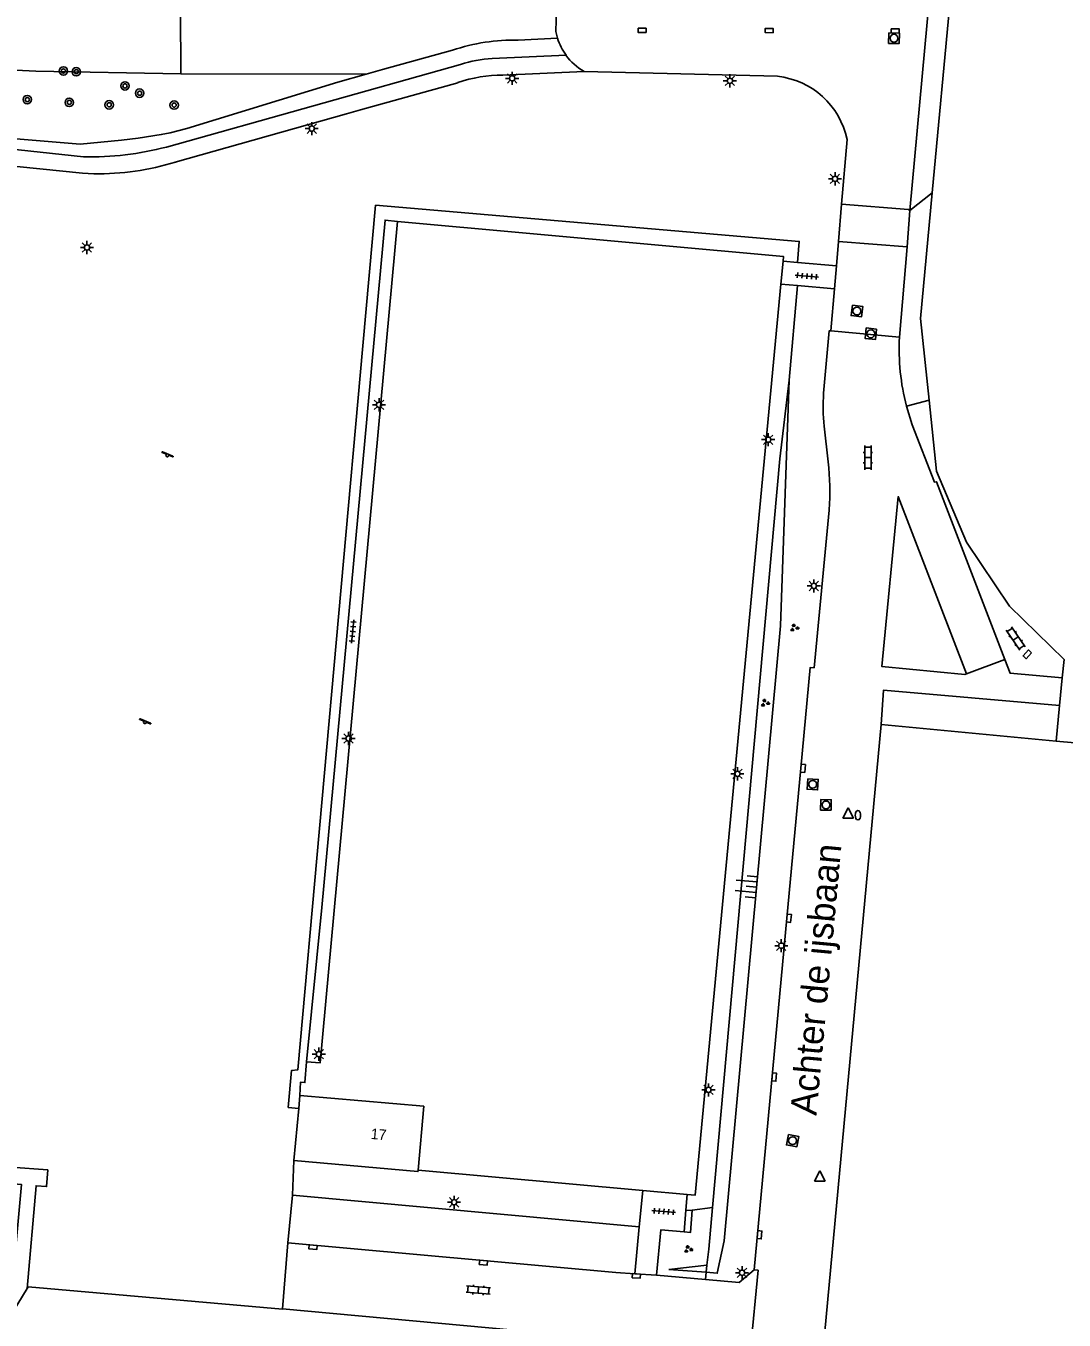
# Model space of a CAD drawing. Extents: x 132994 to 136000, y 393499 to 395512.
# Drawn here: x 133189.3 to 133287.9, y 394586 to 394708.9 of the extents above; entities that cross this region are included whole.
import ezdxf

# ---------------------------------------------------------------- set-up
doc = ezdxf.new("R2010")
doc.units = 0
for name, color, linetype in [('gg-afsc-hekwerk', 7, 'Continuous'), ('gg-anno-huisnummerreeks BGT', 7, 'Continuous'), ('gg-anno-openbare ruimte label', 7, 'Continuous'), ('gg-bbg-hoofdgebouw', 7, 'Continuous'), ('gg-bbg-tussenscheiding', 7, 'Continuous'), ('gg-knt-BGT kruinlijn', 7, 'Continuous'), ('gg-knt-bovenkant onderkant talud', 7, 'Continuous'), ('gg-knt-trap', 7, 'Continuous'), ('gg-knt-verharding', 7, 'Continuous'), ('gg-knt-verharding nz', 7, 'Continuous'), ('gt-grn-groengrens', 7, 'Continuous'), ('gt-symb-boom', 7, 'Continuous'), ('gt-symb-brandkraan', 7, 'Continuous'), ('gt-symb-groenvak', 7, 'Continuous'), ('gt-symb-klinker verharding', 7, 'Continuous'), ('gt-symb-kolk', 7, 'Continuous'), ('gt-symb-kolk center center', 7, 'Continuous'), ('gt-symb-lichtmast', 7, 'Continuous'), ('gt-symb-rioolschacht', 7, 'Continuous'), ('gt-symb-speelvoorziening', 7, 'Continuous'), ('gt-symb-talud symbool', 7, 'Continuous'), ('gt-symb-tegel verharding', 7, 'Continuous'), ('gt-symb-waterafsluiter', 7, 'Continuous')]:
    doc.layers.add(name, color=color, linetype=linetype)

# ---------------------------------------------------------------- blocks, each defined once
blk = doc.blocks.new('gt0-KL1')
at = {"layer": 'gt-symb-klinker verharding'}
for p, q in [((-1.15, 0.3), (1.15, 0.3)), ((-1, -0.3), (-1, 0.3)), ((-0.5, 0.3), (-0.5, 0.45)), ((0, -0.3), (0, 0.3)), ((0.5, 0.3), (0.5, 0.45)), ((1, -0.3), (1, 0.3)), ((-1.15, -0.3), (1.15, -0.3)), ((-0.5, -0.45), (-0.5, -0.3)), ((0.5, -0.45), (0.5, -0.3))]:
    blk.add_line(p, q, dxfattribs=at)
blk = doc.blocks.new('gt0-KOLKCC')
at = {"layer": 'gt-symb-kolk center center'}
blk.add_lwpolyline([(-0.38, 0.2), (0.38, 0.2), (0.38, -0.2), (-0.38, -0.2)], close=True, dxfattribs=at)
blk = doc.blocks.new('gt0-LMAST')
at = {"layer": 'gt-symb-lichtmast'}
for p, q in [((-0.18, 0.17), (-0.45, 0.44)), ((0, 0.25), (0, 0.62)), ((0.17, 0.17), (0.44, 0.44)), ((-0.25, 0), (-0.63, 0)), ((-0.18, -0.18), (-0.45, -0.45)), ((0, -0.25), (0, -0.63)), ((0.44, -0.45), (0.17, -0.18)), ((0.25, 0), (0.62, 0))]:
    blk.add_line(p, q, dxfattribs=at)
blk.add_circle((0, 0), 0.25, dxfattribs=at)
blk = doc.blocks.new('gt0-RS')
at = {"layer": 'gt-symb-rioolschacht'}
blk.add_lwpolyline([(-0.5, -0.5), (0.5, -0.5), (0.5, 0.5), (-0.5, 0.5)], close=True, dxfattribs=at)
blk.add_circle((0, 0), 0.375, dxfattribs=at)
blk = doc.blocks.new('gt0-WAFSL')
at = {"layer": 'gt-symb-waterafsluiter'}
for p, q in [((-0.5, -0.33), (0, 0.67)), ((0, 0.67), (0.5, -0.33)), ((0.5, -0.33), (-0.5, -0.33))]:
    blk.add_line(p, q, dxfattribs=at)
blk = doc.blocks.new('gt0-BR')
at = {"layer": 'gt-symb-brandkraan'}
for centre, radius, start, end in [((-0.24, 0), 0.206, 107.5669, 252.4331), ((0.6, -2.66), 3, 106.892, 107.5669), ((0, -0.69), 0.938, 73.108, 106.892), ((-0.6, -2.66), 3, 72.4331, 73.108), ((0.24, 0), 0.206, 287.567, 72.4331), ((0.6, 2.66), 3, 252.4331, 253.108), ((0, 0.69), 0.938, 253.108, 286.8921), ((-0.6, 2.66), 3, 286.8921, 287.567)]:
    blk.add_arc(centre, radius, start, end, dxfattribs=at)
blk = doc.blocks.new('gt0-TALUD_1')
at = {"layer": 'gt-symb-talud symbool'}
for p, q in [((-1, -1), (-1, 0)), ((-0.5, -2), (-0.5, 0)), ((0, -1), (0, 0)), ((0.5, -2), (0.5, 0)), ((1, -1), (1, 0))]:
    blk.add_line(p, q, dxfattribs=at)
blk = doc.blocks.new('gt0-GRVAK')
at = {"layer": 'gt-symb-groenvak'}
for p, q in [((-0.11, 0.19), (-0.23, 0.24)), ((-0.18, 0.15), (0.09, 0.15)), ((-0.09, 0.21), (-0.16, 0.32)), ((-0.05, 0.21), (-0.05, 0.39)), ((0, 0.21), (0.06, 0.32)), ((0.01, 0.19), (0.13, 0.24)), ((0.26, -0.05), (0.2, 0.06)), ((0.3, -0.05), (0.3, 0.13)), ((0.35, -0.05), (0.41, 0.06)), ((-0.25, -0.23), (-0.36, -0.18)), ((-0.32, -0.26), (-0.05, -0.26)), ((-0.23, -0.21), (-0.29, -0.1)), ((-0.18, -0.2), (-0.18, -0.02)), ((-0.14, -0.21), (-0.07, -0.1)), ((-0.12, -0.23), (0, -0.18)), ((0.24, -0.07), (0.12, -0.02)), ((0.17, -0.11), (0.44, -0.11)), ((0.37, -0.07), (0.49, -0.02))]:
    blk.add_line(p, q, dxfattribs=at)
blk = doc.blocks.new('gt0-KOLK')
at = {"layer": 'gt-symb-kolk'}
blk.add_lwpolyline([(0, 0), (0.37, 0), (0.37, 0.4), (-0.38, 0.4), (-0.38, 0), (0, 0)], dxfattribs=at)
blk = doc.blocks.new('gt0-TEG1')
at = {"layer": 'gt-symb-tegel verharding'}
for p, q in [((-1.13, 0), (1.12, 0)), ((-0.9, -0.25), (-0.9, 0.25)), ((-0.45, -0.25), (-0.45, 0.25)), ((0, -0.25), (0, 0.25)), ((0.45, -0.25), (0.45, 0.25)), ((0.9, -0.25), (0.9, 0.25))]:
    blk.add_line(p, q, dxfattribs=at)
blk = doc.blocks.new('gt0-SV')
at = {"layer": 'gt-symb-speelvoorziening'}
for p, q in [((-0.48, 0.26), (-0.08, 0.1)), ((0.54, -0.08), (-0.45, 0.32)), ((0.13, 0.01), (0.51, -0.14))]:
    blk.add_line(p, q, dxfattribs=at)
for centre, radius, start, end in [((-0.47, 0.29), 0.0369, 63.6251, 252.6602), ((0, -0.01), 0.128, 127.6866, 8.5986), ((0.53, -0.11), 0.0363, 243.5085, 72.5436)]:
    blk.add_arc(centre, radius, start, end, dxfattribs=at)
blk = doc.blocks.new('gt0-BOOM')
at = {"layer": 'gt-symb-boom'}
for radius in [0.4, 0.2]:
    blk.add_circle((0, 0), radius, dxfattribs=at)

msp = doc.modelspace()

# ---------------------------------------------------------------- linework, layer by layer
at = {"layer": 'gg-afsc-hekwerk'}
for p, q in [((133203.96, 394710.33), (133203.99, 394704.3)), ((133260.97, 394684.34), (133261.18, 394686.51)), ((133226.52, 394600.23), (133247.87, 394598.28)), ((133247.87, 394598.28), (133252.07, 394597.9))]:
    msp.add_line(p, q, dxfattribs=at)
for points in [[(133203.99, 394704.3), (133190.2, 394704.56), (133179.49, 394705.09)], [(133224.57, 394690.27), (133217.23, 394610.41), (133215.91, 394610.51)], [(133261.18, 394686.51), (133261.22, 394686.96), (133224.57, 394690.27)], [(133252.07, 394597.9), (133252.83, 394597.83), (133260.97, 394684.34)], [(133215.91, 394610.51), (133215.77, 394608.54), (133215.34, 394608.57), (133215.29, 394607.32)]]:
    msp.add_lwpolyline(points, dxfattribs=at)
at = {"layer": 'gg-bbg-hoofdgebouw'}
for p, q in [((133275.35, 394693.01), (133280.01, 394742.92)), ((133287.7, 394646.95), (133287.44, 394644.33)), ((133287.44, 394644.33), (133287.12, 394640.96)), ((133270.5, 394642.52), (133264.44, 394577.27)), ((133287.12, 394640.96), (133270.5, 394642.52)), ((133215.18, 394606.08), (133215.29, 394607.32)), ((133214.73, 394601.13), (133215.18, 394606.08))]:
    msp.add_line(p, q, dxfattribs=at)
for points in [[(133275.35, 394693.01), (133274.23, 394681.08), (133275.05, 394673.31)], [(133275.05, 394673.31), (133275.76, 394666.58), (133278.6, 394659.83), (133282.7, 394653.76), (133287.87, 394648.69), (133287.7, 394646.95)], [(133215.29, 394607.32), (133227.06, 394606.28), (133226.52, 394600.23)], [(133226.52, 394600.23), (133226.5, 394600.08), (133214.73, 394601.13)]]:
    msp.add_lwpolyline(points, dxfattribs=at)
at = {"layer": 'gg-bbg-tussenscheiding'}
msp.add_line((133287.12, 394640.96), (133358.95, 394634.21), dxfattribs=at)
at = {"layer": 'gg-knt-BGT kruinlijn'}
msp.add_line((133250.32, 394590.8), (133253.89, 394590.52), dxfattribs=at)
msp.add_lwpolyline([(133253.89, 394590.52), (133254.93, 394590.43), (133255.59, 394593.52), (133260.95, 394651.89), (133261.77, 394675.22)], dxfattribs=at)
at = {"layer": 'gg-knt-bovenkant onderkant talud'}
msp.add_line((133253.95, 394591.19), (133250.32, 394590.8), dxfattribs=at)
for points in [[(133261.77, 394675.22), (133260.89, 394667.74), (133254.49, 394596.66)], [(133254.49, 394596.66), (133254.14, 394592.71), (133253.95, 394591.19)]]:
    msp.add_lwpolyline(points, dxfattribs=at)
at = {"layer": 'gg-knt-trap'}
msp.add_lwpolyline([(133270.5, 394642.52), (133270.73, 394645.8), (133287.44, 394644.33)], dxfattribs=at)
at = {"layer": 'gg-knt-verharding'}
for p, q in [((133240.57, 394706.06), (133233.54, 394705.74)), ((133230.56, 394705.2), (133202.62, 394697.35)), ((133234.57, 394704.18), (133242.28, 394704.52)), ((133242.28, 394704.52), (133260.65, 394704.07)), ((133230.29, 394703.46), (133221.06, 394700.87)), ((133221.06, 394700.87), (133219.72, 394700.49)), ((133219.72, 394700.49), (133203.46, 394695.92)), ((133194.74, 394696.43), (133179.16, 394698.07)), ((133267.27, 394698.08), (133266.75, 394691.94)), ((133194.64, 394694.87), (133179.09, 394696.46)), ((133194.64, 394694.87), (133195.73, 394694.81)), ((133273.24, 394691.32), (133275.35, 394693.01)), ((133266.75, 394691.94), (133266.44, 394688.38)), ((133272.96, 394687.86), (133273.24, 394691.32)), ((133266.44, 394688.38), (133266.25, 394686.08)), ((133266.44, 394688.38), (133272.96, 394687.86)), ((133272.24, 394679.29), (133272.96, 394687.86)), ((133261.18, 394686.51), (133262.55, 394686.4)), ((133262.55, 394686.4), (133266.25, 394686.08)), ((133266.25, 394686.08), (133266.06, 394683.9)), ((133260.97, 394684.34), (133262.54, 394684.2)), ((133262.54, 394684.2), (133266.06, 394683.9)), ((133266.06, 394683.9), (133265.72, 394679.9)), ((133272.24, 394679.29), (133265.72, 394679.9)), ((133272.91, 394672.76), (133275.05, 394673.31)), ((133265.1, 394670.85), (133265.46, 394667.45)), ((133264.15, 394647.92), (133265.55, 394662.89)), ((133278.6, 394647.34), (133282.24, 394648.69)), ((133214.16, 394593.33), (133214.58, 394597.84)), ((133214.58, 394597.84), (133247.52, 394594.84)), ((133247.52, 394594.84), (133247.87, 394598.28)), ((133251.95, 394596.43), (133252.07, 394597.9)), ((133251.78, 394594.35), (133251.95, 394596.43)), ((133247.52, 394594.84), (133247.12, 394590.39)), ((133213.63, 394587.06), (133214.16, 394593.33)), ((133247.12, 394590.39), (133249.15, 394590.25)), ((133253.82, 394589.83), (133249.15, 394590.25)), ((133258.08, 394582.98), (133258.81, 394590.74)), ((133258.45, 394590.77), (133258.81, 394590.74)), ((133187.71, 394586.23), (133189.39, 394588.98)), ((133258.08, 394582.98), (133213.63, 394587.06))]:
    msp.add_line(p, q, dxfattribs=at)
for points in [[(133273.24, 394691.32), (133277.45, 394737.08), (133268.78, 394733.04)], [(133239.92, 394719.11), (133239.61, 394708.31), (133239.69, 394707.93), (133239.76, 394707.68)], [(133266.75, 394691.94), (133273.09, 394691.41), (133273.24, 394691.32)], [(133224.57, 394690.27), (133223.38, 394690.41), (133217.37, 394625.14), (133215.91, 394610.51)], [(133265.72, 394679.9), (133265.57, 394679.91), (133265.04, 394673.98)], [(133282.24, 394648.69), (133275.76, 394665.58), (133275.56, 394665.54), (133273.44, 394670.99), (133272.91, 394672.76)], [(133278.6, 394647.34), (133272.13, 394664.16), (133270.58, 394648.03), (133278.44, 394647.27), (133278.6, 394647.34)], [(133264.15, 394647.92), (133263.76, 394647.94), (133262.88, 394638.38), (133261.54, 394624.15), (133258.45, 394590.77)], [(133282.24, 394648.69), (133282.74, 394647.4), (133287.7, 394646.95)], [(133191.35, 394600.24), (133187.83, 394600.49), (133187.72, 394598.96), (133188.84, 394598.86), (133187.75, 394586.66)], [(133191.35, 394600.24), (133191.24, 394598.66), (133190.24, 394598.74), (133189.39, 394588.98)], [(133249.15, 394590.25), (133249.57, 394594.54), (133251.78, 394594.35)], [(133258.45, 394590.77), (133257, 394589.54), (133253.82, 394589.83)], [(133189.39, 394588.98), (133189.49, 394589.15), (133213.63, 394587.02), (133213.63, 394587.06)]]:
    msp.add_lwpolyline(points, dxfattribs=at)
for centre, radius, start, end in [((133245.38, 394709.46), 5.89, 197.5983, 215.2195), ((133234.15, 394694), 11.76, 92.9694, 107.7655), ((133245, 394709.28), 5.48, 215.9695, 240.2224), ((133234.52, 394691.37), 12.81, 89.7619, 109.2627), ((133259.82, 394696.5), 7.61, 11.9111, 83.7875), ((133195.37, 394725.19), 28.77, 268.7522, 284.5907), ((133196.1, 394719.9), 25.09, 269.1665, 287.0792), ((133293.66, 394678.17), 21.45, 176.9894, 194.6002), ((133282.59, 394672.74), 17.6, 175.9855, 186.177), ((133244.4, 394664.76), 21.23, 354.962, 7.2772)]:
    msp.add_arc(centre, radius, start, end, dxfattribs=at)
at = {"layer": 'gg-knt-verharding nz'}
msp.add_lwpolyline([(133214.16, 394593.33), (133245.31, 394590.5), (133247.12, 394590.39)], dxfattribs=at)
at = {"layer": 'gt-grn-groengrens'}
for p, q in [((133236.03, 394707.5), (133239.76, 394707.68)), ((133203.99, 394704.3), (133221.58, 394704.28)), ((133222.46, 394691.82), (133221.26, 394678.48)), ((133261.77, 394675.22), (133262.54, 394684.2)), ((133214.58, 394597.84), (133214.73, 394601.13)), ((133252.35, 394596.39), (133251.95, 394596.43)), ((133252.55, 394596.42), (133252.35, 394596.39)), ((133254.49, 394596.66), (133252.55, 394596.42)), ((133253.89, 394590.52), (133253.82, 394589.83)), ((133253.95, 394591.19), (133253.89, 394590.52))]:
    msp.add_line(p, q, dxfattribs=at)
for points in [[(133221.58, 394704.28), (133223.15, 394704.72), (133229.8, 394706.55)], [(133179.2, 394698.88), (133194.43, 394697.62), (133198.35, 394698.01), (133199.92, 394698.2), (133202.12, 394698.53), (133202.98, 394698.71), (133204.54, 394699.11), (133218.91, 394703.52), (133221.58, 394704.28)], [(133222.46, 394691.82), (133262.72, 394688.39), (133262.55, 394686.4)], [(133221.26, 394678.48), (133215.09, 394609.73), (133214.49, 394609.67), (133214.18, 394606.17), (133215.18, 394606.08)], [(133251.78, 394594.35), (133252.38, 394594.3), (133252.55, 394596.42)]]:
    msp.add_lwpolyline(points, dxfattribs=at)
msp.add_arc((133235.6, 394689.41), 18.09, 88.6268, 108.7025, dxfattribs=at)

# ---------------------------------------------------------------- block references
at = {"layer": 'gt-symb-boom'}
for p in [(133192.83, 394704.57), (133194.05, 394704.5), (133198.68, 394703.15), (133189.4, 394701.85), (133193.39, 394701.59), (133200.07, 394702.46), (133197.18, 394701.36), (133203.35, 394701.33)]:
    msp.add_blockref('gt0-BOOM', p, dxfattribs=at)
at = {"layer": 'gt-symb-brandkraan', "rotation": -89.42706130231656}
msp.add_blockref('gt0-BR', (133268.29, 394633.91), dxfattribs=at)
at = {"layer": 'gt-symb-groenvak'}
for p in [(133262.25, 394651.71), (133259.46, 394644.57), (133252.17, 394592.71)]:
    msp.add_blockref('gt0-GRVAK', p, dxfattribs=at)
at = {"layer": 'gt-symb-klinker verharding'}
for p, rotation in [((133269.24, 394667.86), -90.00000000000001), ((133283.28, 394650.69), 124.40523428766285), ((133232.24, 394588.84), 175.52659354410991)]:
    msp.add_blockref('gt0-KL1', p, dxfattribs=dict(at, rotation=rotation))
at = {"layer": 'gt-symb-kolk'}
for p, rotation in [((133262.88, 394638.38), -95.21999857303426), ((133261.54, 394624.15), -95.39022123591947), ((133260.14, 394609.07), -95.30912697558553), ((133258.75, 394594.1), -95.30109218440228), ((133216.55, 394593.11), 174.80410991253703), ((133232.74, 394591.64), 174.8362574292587), ((133247.26, 394590.38), 175.4032328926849)]:
    msp.add_blockref('gt0-KOLK', p, dxfattribs=dict(at, rotation=rotation))
at = {"layer": 'gt-symb-kolk center center'}
for p, rotation in [((133247.8, 394708.43), -0.1371868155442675), ((133259.87, 394708.4), 178.68242937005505), ((133271.83, 394708.37), -2.0065389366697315), ((133284.39, 394649.19), -131.3529363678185)]:
    msp.add_blockref('gt0-KOLKCC', p, dxfattribs=dict(at, rotation=rotation))
at = {"layer": 'gt-symb-lichtmast'}
for p in [(133235.46, 394703.87), (133256.14, 394703.64), (133216.42, 394699.1), (133266.12, 394694.33), (133195.07, 394687.81), (133222.81, 394672.88), (133259.77, 394669.57), (133264.11, 394655.68), (133219.92, 394641.2), (133256.85, 394637.85), (133261.02, 394621.53), (133217.09, 394611.23), (133254.1, 394607.84), (133229.94, 394597.17), (133257.29, 394590.48)]:
    msp.add_blockref('gt0-LMAST', p, dxfattribs=at)
at = {"layer": 'gt-symb-rioolschacht'}
for p, rotation in [((133271.72, 394707.68), -91.03121266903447), ((133268.2, 394681.78), -97.18187853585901), ((133269.52, 394679.62), 173.62817759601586), ((133264, 394636.85), -94.0121711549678), ((133265.26, 394634.89), 89.08334574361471), ((133262.09, 394603.02), -100.25359802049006)]:
    msp.add_blockref('gt0-RS', p, dxfattribs=dict(at, rotation=rotation))
at = {"layer": 'gt-symb-speelvoorziening'}
for p in [(133202.7, 394668.08), (133200.57, 394642.74)]:
    msp.add_blockref('gt0-SV', p, dxfattribs=at)
at = {"layer": 'gt-symb-talud symbool', "xscale": 0.9991526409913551, "yscale": 0.9991526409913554, "rotation": -95.22557920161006}
msp.add_blockref('gt0-TALUD_1', (133258.67, 394627.08), dxfattribs=at)
at = {"layer": 'gt-symb-tegel verharding'}
for p, rotation in [((133263.45, 394685.1), -4.8778808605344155), ((133220.31, 394651.36), 84.83669318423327), ((133249.86, 394596.29), -4.877880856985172)]:
    msp.add_blockref('gt0-TEG1', p, dxfattribs=dict(at, rotation=rotation))
at = {"layer": 'gt-symb-waterafsluiter'}
for p in [(133267.37, 394633.96), (133264.67, 394599.5)]:
    msp.add_blockref('gt0-WAFSL', p, dxfattribs=at)

# ---------------------------------------------------------------- texts
at = {"layer": 'gg-anno-huisnummerreeks BGT'}
msp.add_text('17', height=1, rotation=354.9, dxfattribs=at).set_placement((133221.99, 394603.19))
at = {"layer": 'gg-anno-openbare ruimte label'}
msp.add_text('Achter de ijsbaan', height=2.5, rotation=84.7, dxfattribs=at).set_placement((133264.35, 394605.36))

doc.saveas('drawing.dxf')
